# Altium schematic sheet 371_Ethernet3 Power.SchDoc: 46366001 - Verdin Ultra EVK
size Letter; Organization: Linear Computing Inc.; Address1: 6415 Northwest Drive; Address2: Mississauga, ON, L4V1X1; Address3: Canada
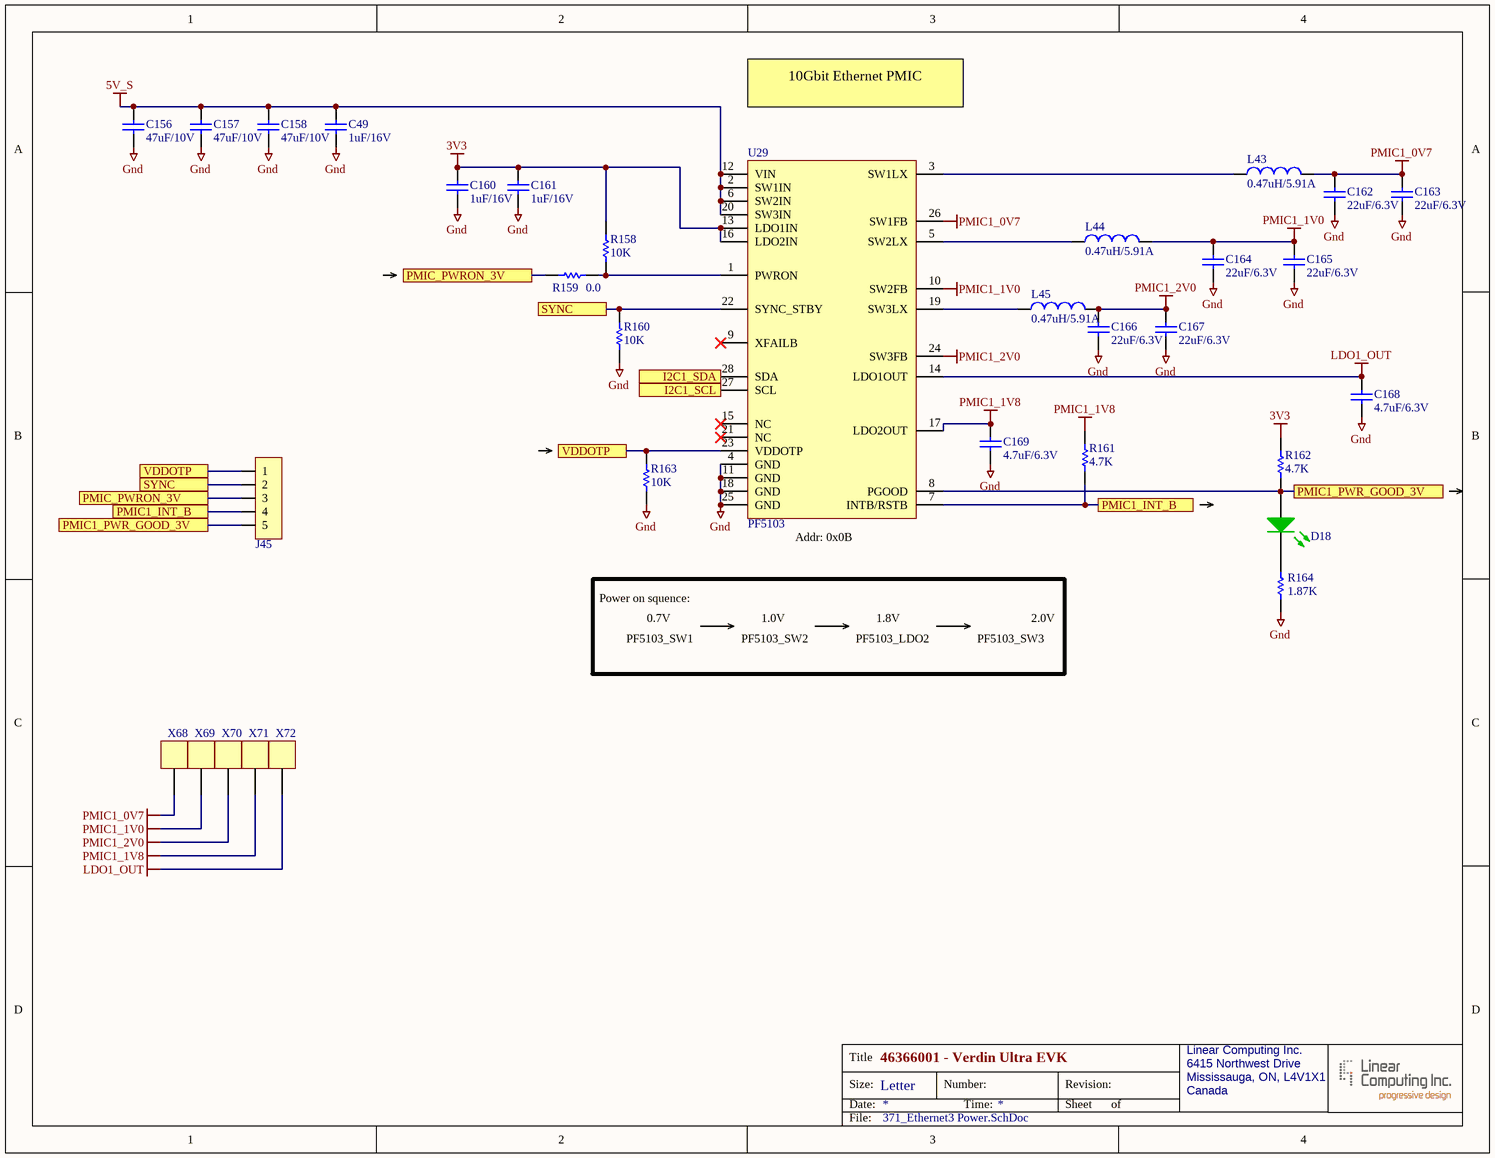
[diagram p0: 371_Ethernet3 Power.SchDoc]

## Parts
C49  value 1uF/16V  [C/0603]  (hidden comment: 0706-Cap-0603-1uF/16V)
C156  value 47uF/10V  [C/0805]  (hidden comment: 1647-Cap-0805-47uF/10V)
C157  value 47uF/10V  [C/0805]  (hidden comment: 1647-Cap-0805-47uF/10V)
C158  value 47uF/10V  [C/0805]  (hidden comment: 1647-Cap-0805-47uF/10V)
C160  value 1uF/16V  [C/0603]  (hidden comment: 0706-Cap-0603-1uF/16V)
C161  value 1uF/16V  [C/0603]  (hidden comment: 0706-Cap-0603-1uF/16V)
C162  value 22uF/6.3V  [C/0603]  (hidden comment: 1008-Cap-0603-22uF/6V3)
C163  value 22uF/6.3V  [C/0603]  (hidden comment: 1008-Cap-0603-22uF/6V3)
C164  value 22uF/6.3V  [C/0603]  (hidden comment: 1008-Cap-0603-22uF/6V3)
C165  value 22uF/6.3V  [C/0603]  (hidden comment: 1008-Cap-0603-22uF/6V3)
C166  value 22uF/6.3V  [C/0603]  (hidden comment: 1008-Cap-0603-22uF/6V3)
C167  value 22uF/6.3V  [C/0603]  (hidden comment: 1008-Cap-0603-22uF/6V3)
C168  value 4.7uF/6.3V  [C/0603]  (hidden comment: 0012-Cap-0603-4.7uF/6.3V)
C169  value 4.7uF/6.3V  [C/0603]  (hidden comment: 0012-Cap-0603-4.7uF/6.3V)
D18  Status  [LED-SMT-0603_APT1608CGCK]  (value not drawn)
J45  000-Hdr-5pin  [HDR1X5]  (value not drawn)
L43  value 0.47uH/5.91A  [VLS3012]  (hidden comment: VLS3012HBX-R47M)
L44  value 0.47uH/5.91A  [VLS3012]  (hidden comment: VLS3012HBX-R47M)
L45  value 0.47uH/5.91A  [VLS3012]  (hidden comment: VLS3012HBX-R47M)
R158  value 10K  [R/0603]  (hidden comment: 0035-Res-0603-10K)
R159  value 0.0  [R/0603]  (hidden comment: 0195-Res-0603-0.0ohm)
R160  value 10K  [R/0603]  (hidden comment: 0035-Res-0603-10K)
R161  value 4.7K  [R/0603]  (hidden comment: 0052-Res-0603-4.7K)
R162  value 4.7K  [R/0603]  (hidden comment: 0052-Res-0603-4.7K)
R163  value 10K  [R/0603]  (hidden comment: 0035-Res-0603-10K)
R164  value 1.87K  [R/0603]  (hidden comment: 0561-Res-0603-1.87K)  (no BOM)
U29  PF5103  [NXP_PF5103]
X68  000-TestPoint  [TestPoint_1]  (value not drawn)
X69  000-TestPoint  [TestPoint_1]  (value not drawn)
X70  000-TestPoint  [TestPoint_1]  (value not drawn)
X71  000-TestPoint  [TestPoint_1]  (value not drawn)
X72  000-TestPoint  [TestPoint_1]  (value not drawn)

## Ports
I2C1_SCL, I2C1_SDA, PMIC1_INT_B, PMIC1_PWR_GOOD_3V, PMIC_PWRON_3V, SYNC, VDDOTP

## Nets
3V3: C160.1 C161.1 R158.1 R162.2 U29.13(LDO1IN) U29.16(LDO2IN)
5V_S: C49.1 C156.2 C157.2 C158.2 U29.2(SW1IN) U29.6(SW2IN) U29.12(VIN) U29.20(SW3IN)
Gnd: C49.2 C156.1 C157.1 C158.1 C160.2 C161.2 C162.1 C163.1 C164.1 C165.1 C166.1 C167.1 C168.1 C169.1 R160.2 R163.2 R164.2 U29.4(GND) U29.11(GND) U29.18(GND) U29.25(GND)
LDO1_OUT: C168.2 U29.14(LDO1OUT) X72.1
PMIC1_0V7: C162.2 C163.2 L43.2 U29.26(SW1FB) X68.1
PMIC1_1V0: C164.2 C165.2 L44.2 U29.10(SW2FB) X69.1
PMIC1_1V8: C169.2 R161.2 U29.17(LDO2OUT) X71.1
PMIC1_2V0: C166.2 C167.2 L45.2 U29.24(SW3FB) X70.1
I2C1_SCL: U29.27(SCL) ; port I2C1_SCL
I2C1_SDA: U29.28(SDA) ; port I2C1_SDA
PMIC1_INT_B: J45.4 R161.1 U29.7(INTB/RSTB) ; port PMIC1_INT_B
PMIC1_PWR_GOOD_3V: D18.1(A) J45.5 R162.1 U29.8(PGOOD) ; port PMIC1_PWR_GOOD_3V
PMIC_PWRON_3V: J45.3 R159.1 ; port PMIC_PWRON_3V
SYNC: J45.2 R160.1 U29.22(SYNC_STBY) ; port SYNC
VDDOTP: J45.1 R163.1 U29.23(VDDOTP) ; port VDDOTP
NetD18_2: D18.2(K) R164.1
NetL43_1: L43.1 U29.3(SW1LX)
NetL44_1: L44.1 U29.5(SW2LX)
NetL45_1: L45.1 U29.19(SW3LX)
NetR158_2: R158.2 R159.2 U29.1(PWRON)

Not connected (* = marked no-connect by the designer): U29 9(XFAILB)* 15(NC)* 21(NC)*

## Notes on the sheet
- 10Gbit Ethernet PMIC
- (near U29) Addr: 0x0B
- Power on squence:
- PF5103_SW1
- 0.7V
- PF5103_SW2
- 1.0V
- PF5103_LDO2
- 1.8V
- PF5103_SW3
- 2.0V

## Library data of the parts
C49 C160 C161 = 0706-Cap-0603-1uF/16V: (-55 to 125 DegC) CAP CER 1UF 16V X7R 0603; Mfr: Samsung Electro-Mechanics America, Inc.; MfrNo: CL10B105MO8NNWC; PN: 706; DR: 1276-6524-6-ND; TR: 1276-6524-2-ND
C156-C158 = 1647-Cap-0805-47uF/10V: (-55 to 85 DegC) CAP CER 47UF 10V X5R 0805; MfrNo: GRM21BR61A476ME15L; Mfr: Murata; PN: 1647; Alt: LMK212BBJ476MG-T,GRM21BR61A476ME15K,C2012X5R1A476M125AC
C162-C167 = 1008-Cap-0603-22uF/6V3: Cap Ceramic 22uF 6.3V X5R 20% SMD 0603 85C T/R; MfrNo: CL10A226MQ8NRNE; Mfr: Samsung; Alt1: GRM188R60J226MEA0D,GRM188R61A226ME15D,CL10A226MQ8NRNC,GRM188R60J226MEA0D,CL10A226MQ8NRNE; PN: 1008
C168 C169 = 0012-Cap-0603-4.7uF/6.3V: CAP CER 4.7UF 6.3V 10% X5R 0603; Mfr: Yageo; MfrNo: CC0603KRX5R5BB475; Alt: 311-1454-1-ND; Alt2: 587-1785-1-ND; PN: 12
D18 = 0333-LED Green 0603: LED GREEN 0603 50mcd; MfrNo: APT1608CGCK; Mfr: Kingbright; Alt: 754-1357-1-ND; Alt2: 160-1834-1-ND; PN: 333; Desc: LED 1.6X0.8MM 570NM GRN CLR SMD; DR: 754-1116-6-ND; DR2: 604-APT1608CGCK
J45 = 000-Hdr-5pin: Header, 5-Pin; Note: PCB footprint only, no parts to buy or assemble
L43-L45 = 1726-Ind-3x3-0.47uH-5.91A: (-40 to 105 DegC) FIXED IND 0.47uH Shielded I:5.91A, Isat:7.46A, 27mOhm typ 3x3x1.2 mm; Mfr: TDK; PN: 1726; Desc: (-40 to 105 DegC) FIXED IND 0.47UHlShielded I:5.91A, Isat:7.46A, 35mOhm typ 3x3x1.2 mm
R158 R160 R163 = 0035-Res-0603-10K: RES 10.0K OHM 1/10W 1% 0603; Mfr: Yageo; MfrNo: RC0603FR-0710KL; Alt: ERJ-3EKF1002V; Alt2: 311-10KLDCT-ND; PN: 35; Desc: RES SMD 10K OHM 1% 1/10W 0603; TR: 311-10.0KHRTR-ND
R159 = 0195-Res-0603-0.0ohm: RES 0.0 OHM 1/10W JUMP 0603; Mfr: Samsung; MfrNo: RC1608J000CS; Alt: 311-0.0GRCT-ND; Alt2: A106051CT-ND; PN: 195; TR: 1276-3510-2-ND
R161 R162 = 0052-Res-0603-4.7K: RES 4.70K OHM 1/10W 1% 0603; MfrNo: RC0603FR-074K7L; Mfr: Yageo; Alt: MCR03FZPFX4701; Alt2: RHM4.70KCFCT-ND; PN: 52; Desc: RES SMD 4.7K OHM 1% 1/10W 0603; TR: 311-4.70KHRTR-ND
R164 = 0561-Res-0603-1.87K: RES SMD 1.87K OHM 1% 1/10W 0603; Mfr: Yageo; MfrNo: RC0603FR-071K87L; Alt: 1276-4669-1-ND; PN: 561; Alt2: P1.87KHCT-ND; TR: 311-1.87KHRTR-ND
U29 = 1844-PF5103: (-40 to 125 DegC) Multi-Channel PMIC 3 LVBUCK Vin:3-5V, Vout:0.5V-3.3V/3.5A and 2 LDO Vin:3-5V, Vout: 0.75-3.3V/0.2A and 0.5A. 2-4.4 MHz. 28 HWQFN; Mfr: NXP; PN: 1844
X68-X72 = 000-TestPoint: Note: this is PCB footprint only, no parts to buy or assemble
